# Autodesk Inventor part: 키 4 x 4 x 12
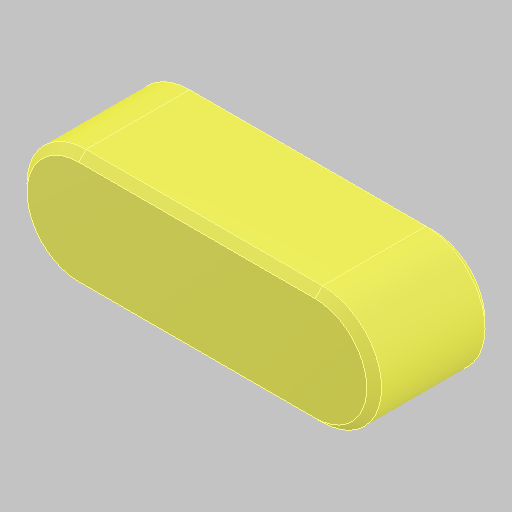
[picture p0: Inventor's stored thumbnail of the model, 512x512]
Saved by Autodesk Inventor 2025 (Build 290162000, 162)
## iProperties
Created: 2024-07
Part Number: 키 4 x 4 x 12
Material: 강철, 연강
Description: 키 및 해당 키홈
Document SubType Name: Modeling
Designer: 현기
Density: 7.85 g/cm^3
Appearance: 기본값
Author: jhkim
Sending System: Autodesk Inventor 2025
Preprocessor: ST-DEVELOPER v20
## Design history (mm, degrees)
feature "Solid1"
node "솔리드1"
